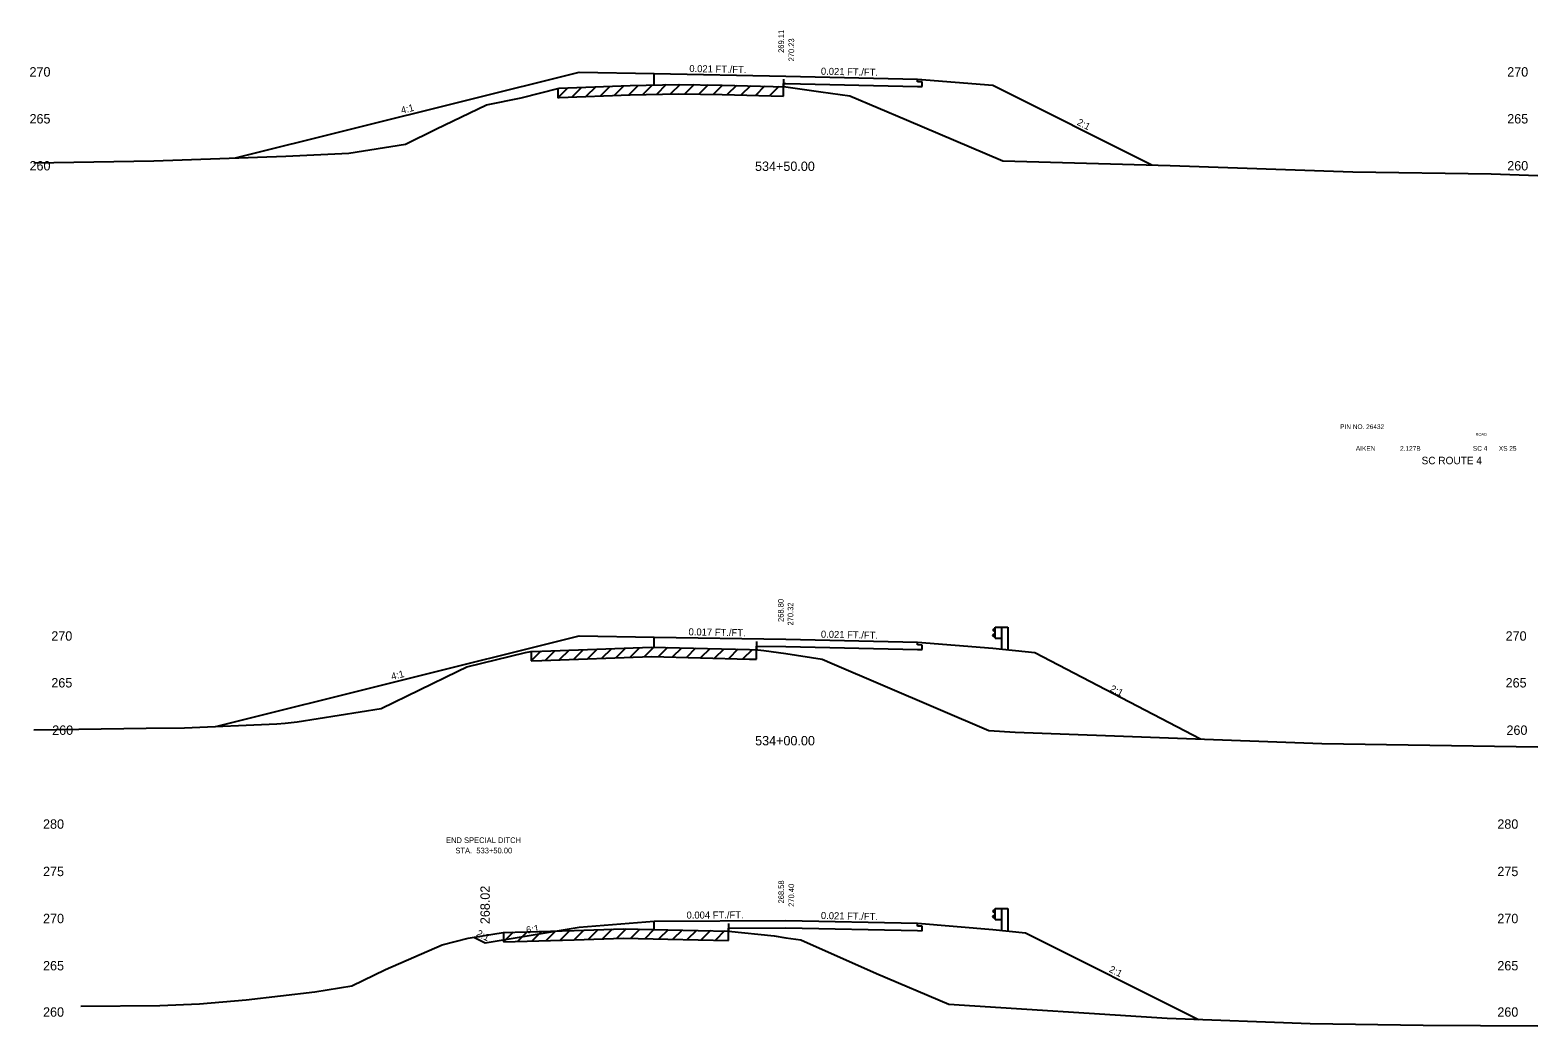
# Model space of a CAD drawing. Extents: x 883 to 1160, y 1002 to 4323.
# Drawn here: x 999.6 to 1160, y 3799.2 to 3905.1 of the extents above; entities that cross this region are included whole.
import ezdxf

# ---------------------------------------------------------------- set-up
doc = ezdxf.new("R2010")
doc.units = 0
for name, color, linetype in [('Level 1', 7, 'Continuous'), ('Level 10', 7, 'Continuous'), ('Level 11', 7, 'Continuous'), ('Level 12', 7, 'Continuous'), ('Level 24', 7, 'Continuous'), ('Level 3', 7, 'Continuous'), ('Level 32', 7, 'Continuous'), ('Level 33', 7, 'Continuous'), ('Level 53', 7, 'Continuous'), ('Level 59', 7, 'Continuous'), ('Level 6', 7, 'Continuous'), ('Level 60', 7, 'Continuous'), ('Level 61', 7, 'Continuous'), ('Level 7', 7, 'Continuous')]:
    doc.layers.add(name, color=color, linetype=linetype)

msp = doc.modelspace()

# ---------------------------------------------------------------- linework, layer by layer
at = {"layer": 'Level 11'}
for p, q in [((1066, 3899.3), (1066, 3900.52)), ((1094, 3899.64), (1094, 3899.94)), ((1094.5, 3899.63), (1094, 3899.64)), ((1094.5, 3899.15), (1094.5, 3899.63)), ((1094, 3899.16), (1094.5, 3899.15)), ((1066, 3839.47), (1066, 3840.57)), ((1094, 3839.73), (1094, 3840.03)), ((1094.5, 3839.72), (1094, 3839.73)), ((1094, 3839.25), (1094.5, 3839.24)), ((1094.5, 3839.24), (1094.5, 3839.72)), ((1066, 3809.45), (1066, 3810.35)), ((1094, 3809.81), (1094, 3810.11)), ((1094.5, 3809.8), (1094, 3809.81)), ((1094.5, 3809.32), (1094.5, 3809.8)), ((1094, 3809.33), (1094.5, 3809.32))]:
    msp.add_line(p, q, dxfattribs=at)
at = {"layer": 'Level 12'}
for p, q in [((1079.73, 3899.12), (1079.73, 3899.45)), ((1079.73, 3899.45), (1080, 3899.45)), ((1080, 3899.45), (1094, 3899.16)), ((1076.86, 3839.22), (1076.86, 3839.6)), ((1076.86, 3839.6), (1080, 3839.55)), ((1080, 3839.55), (1094, 3839.25)), ((1073.91, 3809.6), (1080, 3809.62)), ((1073.91, 3809.29), (1073.91, 3809.6)), ((1080, 3809.62), (1094, 3809.33))]:
    msp.add_line(p, q, dxfattribs=at)
at = {"layer": 'Level 24'}
for p, q in [((1102.27, 3840.45), (1102.27, 3841.62)), ((1102.27, 3841.62), (1102.94, 3841.62)), ((1102.94, 3841.62), (1102.94, 3839.27)), ((1102.94, 3841.62), (1103.6, 3841.62)), ((1103.6, 3841.62), (1103.6, 3839.21)), ((1102.27, 3841.54), (1102, 3841.34)), ((1102, 3841.34), (1102, 3841.29)), ((1102, 3841.29), (1102.27, 3841.09)), ((1102, 3840.77), (1102.27, 3840.97)), ((1102, 3840.72), (1102, 3840.77)), ((1102.27, 3840.52), (1102, 3840.72)), ((1102.27, 3840.45), (1102.94, 3840.45)), ((1102.27, 3811.62), (1102, 3811.42)), ((1102, 3811.42), (1102, 3811.37)), ((1102, 3811.37), (1102.27, 3811.17)), ((1102.27, 3810.53), (1102.27, 3811.69)), ((1102.27, 3811.69), (1102.94, 3811.69)), ((1102.94, 3811.69), (1102.94, 3809.35)), ((1102.94, 3811.69), (1103.6, 3811.69)), ((1103.6, 3811.69), (1103.6, 3809.28)), ((1102, 3810.85), (1102.27, 3811.05)), ((1102, 3810.8), (1102, 3810.85)), ((1102.27, 3810.6), (1102, 3810.8)), ((1102.27, 3810.53), (1102.94, 3810.53))]:
    msp.add_line(p, q, dxfattribs=at)
at = {"layer": 'Level 53'}
for p, q in [((1079.73, 3899.93), (1079.73, 3899.12)), ((1076.86, 3840.08), (1076.86, 3839.22)), ((1073.91, 3810.08), (1073.91, 3809.29))]:
    msp.add_line(p, q, dxfattribs=at)
at = {"layer": 'Level 59'}
for p, q in [((1066, 3900.52), (1080, 3900.23)), ((1080, 3900.23), (1094, 3899.94)), ((1066, 3840.57), (1080, 3840.33)), ((1080, 3840.33), (1094, 3840.03)), ((1066, 3810.35), (1080, 3810.4)), ((1080, 3810.4), (1094, 3810.11))]:
    msp.add_line(p, q, dxfattribs=at)
at = {"layer": 'Level 6'}
for p, q in [((1058, 3900.68), (1066, 3900.52)), ((1094, 3899.94), (1102, 3899.27)), ((1058, 3840.71), (1066, 3840.57)), ((1094, 3840.03), (1102, 3839.37)), ((1102, 3839.37), (1106.5, 3838.92)), ((1058, 3809.69), (1066, 3810.35)), ((1094, 3810.11), (1102, 3809.44)), ((1102, 3809.44), (1105.5, 3809.09))]:
    msp.add_line(p, q, dxfattribs=at)
at = {"layer": 'Level 60'}
for p, q in [((1063.42, 3899.24), (1068.59, 3899.37)), ((1068.59, 3899.37), (1073.21, 3899.3)), ((1048.14, 3897.21), (1051.82, 3897.95)), ((1051.82, 3897.95), (1055.88, 3898.96)), ((1055.88, 3898.96), (1063.42, 3899.24)), ((1073.21, 3899.3), (1080, 3899.11)), ((1080, 3899.11), (1083.71, 3898.57)), ((1083.71, 3898.57), (1086.8, 3898.15)), ((1086.8, 3898.15), (1092.82, 3895.61)), ((1042.77, 3894.59), (1048.14, 3897.21)), ((1039.54, 3893.01), (1042.77, 3894.59)), ((1092.82, 3895.61), (1103.09, 3891.22)), ((1033.51, 3892.05), (1039.54, 3893.01)), ((1012.74, 3891.22), (1026.81, 3891.74)), ((1026.81, 3891.74), (1033.51, 3892.05)), ((1000, 3891.03), (1012.74, 3891.22)), ((1103.09, 3891.22), (1120.87, 3890.75)), ((1120.87, 3890.75), (1140.33, 3890.05)), ((1140.33, 3890.05), (1155.03, 3889.84)), ((1155.03, 3889.84), (1160, 3889.69)), ((1046.07, 3837.38), (1052.3, 3838.94)), ((1052.3, 3838.94), (1052.87, 3839.03)), ((1052.87, 3839.03), (1054.03, 3839.06)), ((1054.03, 3839.06), (1065.69, 3839.48)), ((1065.69, 3839.48), (1076.14, 3839.23)), ((1076.14, 3839.23), (1077.01, 3839.21)), ((1077.01, 3839.21), (1077.66, 3839.14)), ((1077.66, 3839.14), (1080, 3838.8)), ((1080, 3838.8), (1083.86, 3838.23)), ((1036.96, 3832.98), (1045.11, 3836.95)), ((1045.11, 3836.95), (1046.07, 3837.38)), ((1083.86, 3838.23), (1084.91, 3837.76)), ((1084.91, 3837.76), (1101.6, 3830.63)), ((1028, 3831.56), (1036.96, 3832.98)), ((1000, 3830.71), (1011.95, 3830.87)), ((1011.95, 3830.87), (1016.03, 3830.89)), ((1016.03, 3830.89), (1025.86, 3831.33)), ((1025.86, 3831.33), (1026.73, 3831.41)), ((1026.73, 3831.41), (1028, 3831.56)), ((1101.6, 3830.63), (1104.38, 3830.45)), ((1104.38, 3830.45), (1137.02, 3829.23)), ((1137.02, 3829.23), (1160, 3828.89)), ((1057.46, 3809.34), (1062.72, 3809.53)), ((1062.72, 3809.53), (1067.44, 3809.42)), ((1043.44, 3807.83), (1046.2, 3808.53)), ((1046.2, 3808.53), (1049.94, 3809.12)), ((1049.94, 3809.12), (1057.46, 3809.34)), ((1067.44, 3809.42), (1073.89, 3809.29)), ((1073.89, 3809.29), (1078.77, 3808.76)), ((1078.77, 3808.76), (1080, 3808.58)), ((1080, 3808.58), (1081.6, 3808.34)), ((1081.6, 3808.34), (1089.65, 3804.78)), ((1037.4, 3805.18), (1043.44, 3807.83)), ((1033.82, 3803.44), (1037.4, 3805.18)), ((1089.65, 3804.78), (1097.33, 3801.5)), ((1029.9, 3802.82), (1033.82, 3803.44)), ((1013.41, 3801.35), (1017.62, 3801.54)), ((1017.62, 3801.54), (1022.58, 3801.97)), ((1022.58, 3801.97), (1029.9, 3802.82)), ((1097.33, 3801.5), (1120.55, 3800.02)), ((1005, 3801.31), (1013.41, 3801.35)), ((1120.55, 3800.02), (1135.77, 3799.45)), ((1135.77, 3799.45), (1147.79, 3799.27)), ((1147.79, 3799.27), (1160, 3799.2))]:
    msp.add_line(p, q, dxfattribs=at)
at = {"layer": 'Level 61'}
for p, q in [((1068.77, 3899.37), (1067.74, 3898.35)), ((1070.23, 3899.35), (1069.25, 3898.36)), ((1056.8, 3899), (1055.73, 3897.93)), ((1055.73, 3898.93), (1055.73, 3897.93)), ((1055.73, 3897.93), (1055.88, 3897.96)), ((1055.88, 3897.96), (1063.42, 3898.24)), ((1058.27, 3899.05), (1057.23, 3898.01)), ((1059.77, 3899.1), (1058.73, 3898.07)), ((1061.27, 3899.16), (1060.23, 3898.12)), ((1062.77, 3899.21), (1061.74, 3898.18)), ((1064.27, 3899.26), (1063.24, 3898.23)), ((1063.42, 3898.24), (1068.59, 3898.37)), ((1065.77, 3899.3), (1064.74, 3898.27)), ((1067.27, 3899.34), (1066.24, 3898.31)), ((1068.59, 3898.37), (1073.21, 3898.3)), ((1071.73, 3899.32), (1070.75, 3898.34)), ((1073.24, 3899.29), (1072.25, 3898.31)), ((1073.21, 3898.3), (1079.73, 3898.12)), ((1074.73, 3899.25), (1073.75, 3898.28)), ((1076.23, 3899.21), (1075.26, 3898.24)), ((1077.73, 3899.17), (1076.76, 3898.2)), ((1079.24, 3899.13), (1078.26, 3898.16)), ((1079.73, 3898.12), (1079.73, 3899.12)), ((1053.92, 3839.06), (1052.89, 3838.03)), ((1052.89, 3839.03), (1052.89, 3838.03)), ((1054.03, 3838.06), (1065.69, 3838.48)), ((1055.43, 3839.11), (1054.39, 3838.07)), ((1056.93, 3839.16), (1055.89, 3838.13)), ((1058.43, 3839.22), (1057.4, 3838.18)), ((1059.94, 3839.27), (1058.9, 3838.24)), ((1061.44, 3839.33), (1060.4, 3838.29)), ((1062.94, 3839.38), (1061.9, 3838.34)), ((1064.44, 3839.43), (1063.41, 3838.4)), ((1065.93, 3839.47), (1064.91, 3838.45)), ((1065.69, 3838.48), (1076.14, 3838.23)), ((1067.39, 3839.44), (1066.41, 3838.46)), ((1068.89, 3839.4), (1067.91, 3838.43)), ((1070.39, 3839.37), (1069.42, 3838.39)), ((1071.9, 3839.33), (1070.92, 3838.35)), ((1073.4, 3839.29), (1072.42, 3838.32)), ((1074.9, 3839.26), (1073.92, 3838.28)), ((1076.41, 3839.22), (1075.43, 3838.25)), ((1076.86, 3838.22), (1076.86, 3839.22)), ((1052.89, 3838.03), (1054.03, 3838.06)), ((1076.14, 3838.23), (1076.86, 3838.22)), ((1063, 3809.52), (1061.98, 3808.5)), ((1050.99, 3809.15), (1049.96, 3808.12)), ((1049.96, 3809.12), (1049.96, 3808.12)), ((1049.96, 3808.12), (1057.46, 3808.34)), ((1052.49, 3809.2), (1051.46, 3808.17)), ((1054, 3809.24), (1052.96, 3808.21)), ((1055.5, 3809.28), (1054.47, 3808.25)), ((1057, 3809.33), (1055.97, 3808.3)), ((1057.46, 3808.34), (1062.72, 3808.53)), ((1058.51, 3809.38), (1057.47, 3808.34)), ((1060.01, 3809.43), (1058.97, 3808.39)), ((1061.52, 3809.49), (1060.48, 3808.45)), ((1062.72, 3808.53), (1067.44, 3808.42)), ((1064.46, 3809.49), (1063.48, 3808.51)), ((1065.96, 3809.45), (1064.98, 3808.47)), ((1067.47, 3809.42), (1066.49, 3808.44)), ((1067.44, 3808.42), (1073.89, 3808.29)), ((1068.97, 3809.39), (1067.99, 3808.41)), ((1070.48, 3809.36), (1069.49, 3808.38)), ((1071.98, 3809.33), (1070.99, 3808.35)), ((1073.48, 3809.3), (1072.5, 3808.32)), ((1073.89, 3808.29), (1073.91, 3808.29)), ((1073.91, 3808.29), (1073.91, 3809.29))]:
    msp.add_line(p, q, dxfattribs=at)
at = {"layer": 'Level 7'}
for p, q in [((1021.43, 3891.54), (1058, 3900.68)), ((1102, 3899.27), (1118.93, 3890.81)), ((1019.35, 3831.04), (1058, 3840.71)), ((1106.5, 3838.92), (1124.1, 3829.72)), ((1048, 3808.02), (1058, 3809.69)), ((1046.8, 3808.62), (1048, 3808.02)), ((1105.5, 3809.09), (1123.9, 3799.89))]:
    msp.add_line(p, q, dxfattribs=at)

# ---------------------------------------------------------------- texts
at = {"layer": 'Level 1'}
for s, height, p in [('534+50.00', 1, (1076.72, 3890.16)), ('PIN NO. 26432', 0.5, (1138.97, 3862.7)), ('AIKEN', 0.5, (1140.64, 3860.39)), (' 2.127B', 0.5, (1145.15, 3860.39)), ('SC 4', 0.5, (1153.09, 3860.39)), ('XS 25', 0.5, (1155.85, 3860.39)), ('SC ROUTE 4', 0.8, (1147.63, 3858.95)), ('534+00.00', 1, (1076.73, 3829.04))]:
    msp.add_text(s, height=height, dxfattribs=at).set_placement(p)
at = {"layer": 'Level 10'}
for s, p in [('269.11', (1079.8, 3902.72)), ('268.80', (1079.76, 3842.17)), ('268.58', (1079.8, 3812.22))]:
    msp.add_text(s, height=0.6, rotation=90, dxfattribs=at).set_placement(p)
at = {"layer": 'Level 3'}
for s, height, p in [(' 270', 1, (999.16, 3900.2)), (' 270', 1, (1156.37, 3900.2)), (' 265', 1, (999.16, 3895.21)), (' 265', 1, (1156.37, 3895.21)), (' 260', 1, (999.16, 3890.21)), (' 260', 1, (1156.37, 3890.21)), ('ROAD', 0.3, (1153.38, 3861.98)), (' 270', 1, (1001.48, 3840.18)), (' 270', 1, (1156.2, 3840.18)), (' 265', 1, (1001.48, 3835.2)), (' 265', 1, (1156.2, 3835.2)), (' 260', 1, (1001.57, 3830.16)), (' 260', 1, (1156.29, 3830.16)), (' 280', 1, (1000.6, 3820.17)), (' 280', 1, (1155.32, 3820.17)), (' 275', 1, (1000.6, 3815.13)), (' 275', 1, (1155.32, 3815.13)), (' 270', 1, (1000.6, 3810.12)), (' 270', 1, (1155.32, 3810.12)), (' 265', 1, (1000.6, 3805.1)), (' 265', 1, (1155.32, 3805.1)), (' 260', 1, (1000.6, 3800.17)), (' 260', 1, (1155.32, 3800.17))]:
    msp.add_text(s, height=height, dxfattribs=at).set_placement(p)
at = {"layer": 'Level 32'}
for s, rotation, p in [('0.021 FT./FT.', 358.8084, (1069.72, 3900.69)), ('0.021 FT./FT.', 358.8084, (1083.72, 3900.4)), ('4:1', 14.0362, (1039.14, 3896.23)), ('2:1', 333.435, (1110.91, 3895.1)), ('0.017 FT./FT.', 359.0092, (1069.64, 3840.75)), ('0.021 FT./FT.', 358.8084, (1083.72, 3840.5)), ('4:1', 14.0362, (1038.1, 3835.99)), ('2:1', 333.435, (1114.41, 3834.84)), ('0.004 FT./FT.', 0.2009, (1069.43, 3810.61)), ('0.021 FT./FT.', 358.8084, (1083.72, 3810.57)), ('6:1', 9.4623, (1052.43, 3809.01)), ('2:1', 333.435, (1047, 3808.8)), ('2:1', 333.435, (1114.31, 3804.97))]:
    msp.add_text(s, height=0.75, rotation=rotation, dxfattribs=at).set_placement(p)
for s, p in [('END SPECIAL DITCH', (1043.84, 3818.65)), ('STA.  533+50.00', (1044.84, 3817.55))]:
    msp.add_text(s, height=0.6, dxfattribs=at).set_placement(p)
at = {"layer": 'Level 33'}
msp.add_text('268.02', height=1, rotation=90, dxfattribs=at).set_placement((1048.5, 3810.02))
at = {"layer": 'Level 59'}
for s, p in [(' 270.23', (1080.88, 3901.59)), (' 270.32', (1080.79, 3841.57)), (' 270.40', (1080.88, 3811.64))]:
    msp.add_text(s, height=0.6, rotation=90, dxfattribs=at).set_placement(p)

doc.saveas('drawing.dxf')
